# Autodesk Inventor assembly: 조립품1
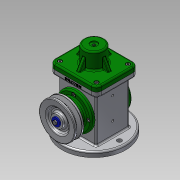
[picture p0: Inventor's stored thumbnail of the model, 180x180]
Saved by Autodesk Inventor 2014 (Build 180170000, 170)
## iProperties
Created: 2018-10
Part Number: 조립품1
Document SubType Name: Assembly
Designer: Administrator
Author: Administrator
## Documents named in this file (18)
- C:\Users\Administrator\Desktop\481007V1045\조립품1.iam
- C:\Users\Administrator\Desktop\481007V1045\본체.ipt
- C:\Users\Administrator\Desktop\481007V1045\E-링.ipt
- C:\Users\Administrator\Desktop\481007V1045\V-벨트풀리.ipt
- C:\Users\Administrator\Desktop\481007V1045\덮개.ipt
- C:\Users\Administrator\Desktop\481007V1045\뒤커버.ipt
- C:\Users\Administrator\Desktop\481007V1045\링크.ipt
- C:\Users\Administrator\Desktop\481007V1045\베어링 17 x 40 x 12.ipt
- C:\Users\Administrator\Desktop\481007V1045\볼트 M4 x 8.ipt
- C:\Users\Administrator\Desktop\481007V1045\볼트 M4 x 10.ipt
- C:\Users\Administrator\Desktop\481007V1045\슬라이더.ipt
- C:\Users\Administrator\Desktop\481007V1045\앞커버.ipt
- C:\Users\Administrator\Desktop\481007V1045\오일 실 17 30 8.ipt
- C:\Users\Administrator\Desktop\481007V1045\와셔 4x16.ipt
- C:\Users\Administrator\Desktop\481007V1045\클레비스 핀 6 x 22.ipt
- 클레비스 핀 6 x 22.ipt
- C:\Users\Administrator\Desktop\481007V1045\키 4 x 4 x 12.ipt
- C:\Users\Administrator\Desktop\481007V1045\편심축.ipt
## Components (2 placed, 2 different names)
1. E-링:1
2. V-벨트풀리:1 — 플러쉬:2
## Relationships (1: Flush 1)
- 플러쉬:2 [Flush]: V-벨트풀리:1
